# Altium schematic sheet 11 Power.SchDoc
size 420 x 297 mm; DocumentNumber: 11; SheetNumber: 11; SheetTotal: 12
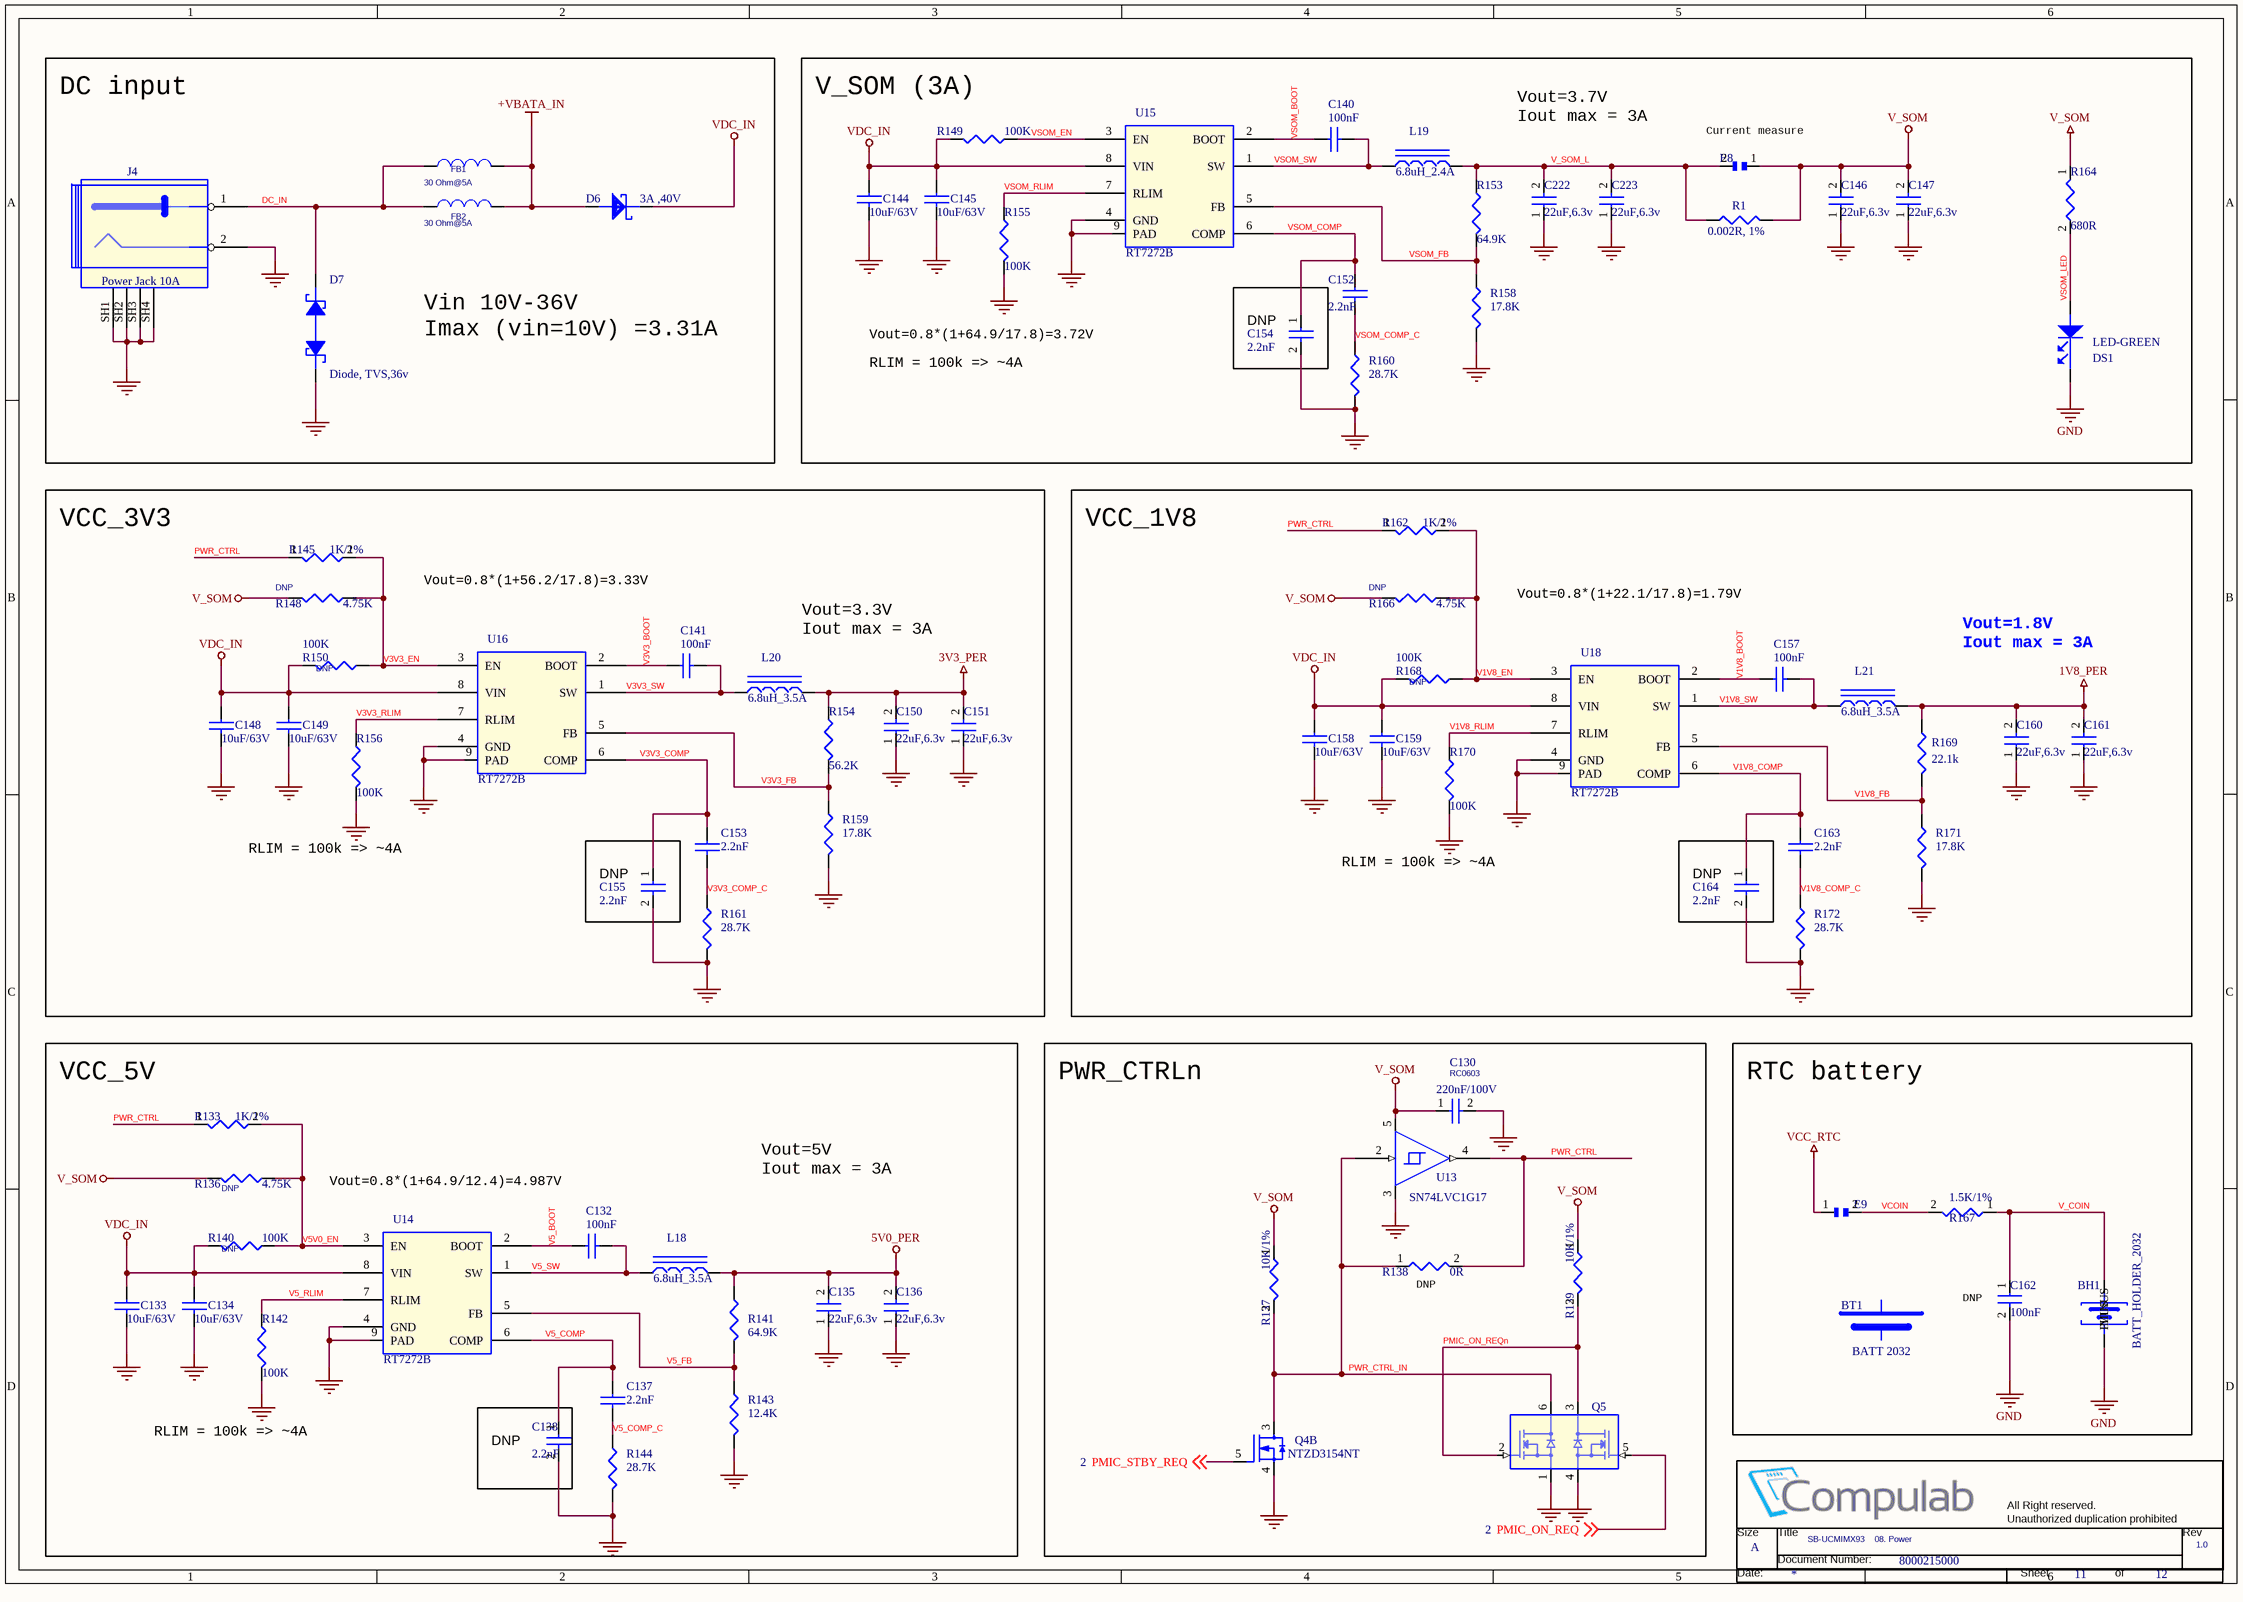
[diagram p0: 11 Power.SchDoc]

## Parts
*  Title: SB-UCMIMX93    08. Power  Doc: 8000215000  RevCode: 1.0  Page Size: A  Page Number: 11  Page Count: 12  (hidden comment: CompuLabTitleBlk)  (graphical)
BH1  BATT_HOLDER_2032  [BATTH20MM]
BT1  BATT 2032  [1X2THHDR]  (mechanical)
C130  220nF/100V  [RC0603]
C132  100nF  [RC0402]
C133  10uF/63V  [C1210H2_5]
C134  10uF/63V  [C1210H2_5]
C135  22uF,6.3v  [RC0603]
C136  22uF,6.3v  [RC0603]
C137  2.2nF  [RC0402]
C138  2.2nF  [RC0402]
C140  100nF  [RC0402]
C141  100nF  [RC0402]
C144  10uF/63V  [C1210H2_5]
C145  10uF/63V  [C1210H2_5]
C146  22uF,6.3v  [RC0603]
C147  22uF,6.3v  [RC0603]
C148  10uF/63V  [C1210H2_5]
C149  10uF/63V  [C1210H2_5]
C150  22uF,6.3v  [RC0603]
C151  22uF,6.3v  [RC0603]
C152  2.2nF  [RC0402]
C153  2.2nF  [RC0402]
C154  2.2nF  [RC0402]
C155  2.2nF  [RC0402]
C157  100nF  [RC0402]
C158  10uF/63V  [C1210H2_5]
C159  10uF/63V  [C1210H2_5]
C160  22uF,6.3v  [RC0603]
C161  22uF,6.3v  [RC0603]
C162  100nF  [RC0402]
C163  2.2nF  [RC0402]
C164  2.2nF  [RC0402]
C222  22uF,6.3v  [RC0603]
C223  22uF,6.3v  [RC0603]
D6  3A ,40V  [DO-214AC]
D7  Diode, TVS,36v  [SOD-323]
DS1  LED-GREEN  [LED-1206]
E8  HDR1X2  [1X2THHDR]  (value not drawn)
E9  HDR1X2  [1X2THHDR]  (value not drawn)
FB1  30 Ohm@5A  [FB0603]
FB2  30 Ohm@5A  [FB0603]
J4  Power Jack 10A  [PJ-0810-TH]
L18  6.8uH_3.5A  [IND6x5_5x3]
L19  6.8uH_2.4A  [IND6x5_5x3]
L20  6.8uH_3.5A  [IND6x5_5x3]
L21  6.8uH_3.5A  [IND6x5_5x3]
Q4  NTZD3154NT  [SOT-563-6]  (part B of 2)
Q5  0.5A,20V,Vgs max 6V  [SOT-563-6]  (value not drawn)
R1  0.002R, 1%  [R1206]
R133  1K/1%  [RC0402]
R136  4.75K  CLABCONF0: DNP  [RC0402]
R137  10K/1%  [RC0402]
R138  0R  [RC0402]
R139  10K/1%  [RC0402]
R140  100K  CLABCONF0: DNP  [RC0402]
R141  64.9K  [RC0402]
R142  100K  [RC0402]
R143  12.4K  [RC0402]
R144  28.7K  [RC0402]
R145  1K/1%  [RC0402]
R148  4.75K  CLABCONF0: DNP  [RC0402]
R149  100K  [RC0402]
R150  100K  CLABCONF0: DNP  [RC0402]
R153  64.9K  [RC0402]
R154  56.2K  [RC0402]
R155  100K  [RC0402]
R156  100K  [RC0402]
R158  17.8K  [RC0402]
R159  17.8K  [RC0402]
R160  28.7K  [RC0402]
R161  28.7K  [RC0402]
R162  1K/1%  [RC0402]
R164  680R  [RC0402]
R166  4.75K  CLABCONF0: DNP  [RC0402]
R167  1.5K/1%  [RC0402]
R168  100K  CLABCONF0: DNP  [RC0402]
R169  22.1k  [RC0402]
R170  100K  [RC0402]
R171  17.8K  [RC0402]
R172  28.7K  [RC0402]
U13  SN74LVC1G17  [SC70]
U14  RT7272B  [PSOP-8-2X2]
U15  RT7272B  [PSOP-8-2X2]
U16  RT7272B  [PSOP-8-2X2]
U18  RT7272B  [PSOP-8-2X2]

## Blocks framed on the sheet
DC input: D6 D7 FB1 FB2 J4
V_SOM (3A): C140 C144-C147 C152 C222 C223 DS1 E8 L19 R1 R149 R153 R155 R158 R160 R164 U15
DNP: C154
VCC_3V3: C141 C148-C151 C153 L20 R145 R148 R150 R154 R156 R159 R161 U16
VCC_1V8: C157-C161 C163 L21 R162 R166 R168-R172 U18
DNP: C155
DNP: C164
VCC_5V: C132-C137 L18 R133 R136 R140-R144 U14
PWR_CTRLn: C130 Q4 Q5 R137-R139 U13
RTC battery: BH1 BT1 C162 E9 R167
DNP: C138

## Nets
1V8_PER: C160.2 C161.2 L21.2 R169.1
3V3_PER: C150.2 C151.2 L20.2 R154.1
5V0_PER: C135.2 C136.2 L18.2 R141.1
+VBATA_IN: D6.ANODE FB1.2 FB2.2
GND: BH1.1(MINUS) C130.2 C133.2 C134.2 C135.1 C136.1 C138.2 C144.2 C145.2 C146.1 C147.1 C148.2 C149.2 C150.1 C151.1 C154.2 C155.2 C158.2 C159.2 C160.1 C161.1 C162.2 C164.2 C222.1 C223.1 D7.ANODE DS1.CATHODE J4.2(R) J4.SH1 J4.SH2 J4.SH3 J4.SH4 Q4.4(S) Q5.1(S1) Q5.4(S2) R142.2 R143.2 R144.2 R155.2 R156.2 R158.2 R159.2 R160.2 R161.2 R170.2 R171.2 R172.2 U13.3(GND) U14.4(GND) U14.9(PAD) U15.4(GND) U15.9(PAD) U16.4(GND) U16.9(PAD) U18.4(GND) U18.9(PAD)
V_SOM: C130.1 C146.2 C147.2 E8.1 R1.2 R136.2 R137.1 R139.1 R148.2 R164.1 R166.2 U13.5(VCC)
VCC_RTC: E9.1
VDC_IN: C133.1 C134.1 C144.1 C145.1 C148.1 C149.1 C158.1 C159.1 D6.CATHODE R140.2 R149.2 R150.2 R168.2 U14.8(VIN) U15.8(VIN) U16.8(VIN) U18.8(VIN)
DC_IN: D7.CATHODE FB1.1 FB2.1 J4.1(CENTRAL)
PMIC_ON_REQ: Q5.5(G2) ; off-sheet PMIC_ON_REQ
PMIC_ON_REQn: Q5.2(G1) Q5.3(D2) R139.2
PMIC_STBY_REQ: Q4.5(G) ; off-sheet PMIC_STBY_REQ
PWR_CTRL: R133.1 R138.2 R145.1 R162.1 U13.4(Y)
PWR_CTRL_IN: Q4.3(D) Q5.6(D1) R137.2 R138.1 U13.2(A)
V1V8_BOOT: C157.1 U18.2(BOOT)
V1V8_COMP: C163.1 C164.1 U18.6(COMP)
V1V8_COMP_C: C163.2 R172.1
V1V8_EN: R162.2 R166.1 R168.1 U18.3(EN)
V1V8_FB: R169.2 R171.1 U18.5(FB)
V1V8_RLIM: R170.1 U18.7(RLIM)
V1V8_SW: C157.2 L21.1 U18.1(SW)
V3V3_BOOT: C141.1 U16.2(BOOT)
V3V3_COMP: C153.1 C155.1 U16.6(COMP)
V3V3_COMP_C: C153.2 R161.1
V3V3_EN: R145.2 R148.1 R150.1 U16.3(EN)
V3V3_FB: R154.2 R159.1 U16.5(FB)
V3V3_RLIM: R156.1 U16.7(RLIM)
V3V3_SW: C141.2 L20.1 U16.1(SW)
V5_BOOT: C132.1 U14.2(BOOT)
V5_COMP: C137.1 C138.1 U14.6(COMP)
V5_COMP_C: C137.2 R144.1
V5_FB: R141.2 R143.1 U14.5(FB)
V5_RLIM: R142.1 U14.7(RLIM)
V5_SW: C132.2 L18.1 U14.1(SW)
V5V0_EN: R133.2 R136.1 R140.1 U14.3(EN)
V_COIN: BH1.2(PLUS) C162.1 R167.1
V_SOM_L: C222.2 C223.2 E8.2 L19.2 R1.1 R153.1
VCOIN: E9.2 R167.2
VSOM_BOOT: C140.1 U15.2(BOOT)
VSOM_COMP: C152.1 C154.1 U15.6(COMP)
VSOM_COMP_C: C152.2 R160.1
VSOM_EN: R149.1 U15.3(EN)
VSOM_FB: R153.2 R158.1 U15.5(FB)
VSOM_LED: DS1.ANODE R164.2
VSOM_RLIM: R155.1 U15.7(RLIM)
VSOM_SW: C140.2 L19.1 U15.1(SW)

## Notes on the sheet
- Vout=3.7V
  Iout max = 3A
- (near E8) Current measure
- Vin 10V-36V
  Imax (vin=10V) =3.31A
- Vout=0.8*(1+64.9/17.8)=3.72V
- RLIM = 100k => ~4A
- Vout=0.8*(1+56.2/17.8)=3.33V
- Vout=3.3V
  Iout max = 3A
- Vout=0.8*(1+22.1/17.8)=1.79V
- Vout=1.8V
  Iout max = 3A
- Vout=0.8*(1+64.9/12.4)=4.987V
- Vout=5V
  Iout max = 3A
- (near R138) DNP
- (near C162) DNP

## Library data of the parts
BH1 = BATT_HOLDER_0: P/N: 190Z00201
BT1 = BATT 2032: P/N: 210C30002
C130 = 100nF, 10V, X7R, 10%, 0402_Dup1: P/N: 151E22410S
C132 C140 C141 C157 = 100nF, 10V, X7R, 10%, 0402_0: P/N: 151B10400S; Group: LAN2
C133 C134 C148 C149 C158 C159 = 22uF/25V: P/N: 151E10680S
C135 C136 C146 C147 C150 C151 C160 C161 C222 C223 = 100nF, 10V, X7R, 10%, 0402: P/N: 151B22610S
C137 C152 C153 C163 = 2.2nF, 50V, X7R, 10%, 0402: P/N: 151D22200S
C138 C154 C155 C164 = 2.2nF, 50V, X7R, 10%, 0402_Dup1: P/N: 151D22200S; CLABCONF0: DNP
C144 C145 = 22uF/25V: P/N: 151D10630S
C162 = 100nF, 10V, X7R, 10%, 0402_Dup1: P/N: 151B10400S; CLABCONF0: DNP
D6 = Diode Shotky,5A,30V_0: P/N: 130E40001S
D7 = 1A Schottky Barrier Rectifier_1: P/N: 132D10080S
DS1 = LED-GREEN 1206_2: P/N: 139A10020S
E8 E9 = HDR 1x2 100MIL TH JUMPER: P/N: 190C00200
FB1 FB2 = Ferrite bead , 30 Ohm@5A: P/N: 147D30000S
J4 = DC Jack ,5.5/2.5,10A,20V: P/N: 180K00200
L18 L20 L21 = IND 6.8uH 3.5A: P/N: 147A6R802S
L19 = IND 6.8uH 3.5A: P/N: 147A6R804S
Q4 = N-MOSFET_Dual: P/N: 131D31540S
Q5 = DUAL N-MOSFET, 0.5A 20V: P/N: 131D31540S
R1 = RESISTOR: P/N: 161F00211S
R133 R145 R162 = 1K,1%,0402,1/16W: P/N: 161C10011S; Group: CAN
R136 R148 R166 = 100K, 0402_0: P/N: 161C47511S
R137 R139 = 10K,1%,0402,1/16W: P/N: 161C10021S
R138 = 0R, 0402: P/N: 161C00005S; CLABCONF0: DNP
R140 R142 R149 R150 R155 R156 R168 R170 = 100K, 0402_0: P/N: 161C10035S
R141 R153 = 10.5K/1%,0402: P/N: 161C64921S
R143 = 2.37K/1%, 0402: P/N: 161C12421S
R144 R160 R161 R172 = 40.2k/1%: P/N: 161C28721S
R154 = 10.5K/1%,0402: P/N: 161C56221S
R158 R159 R171 = 2.37K/1%, 0402: P/N: 161C17821S
R164 = 47K, 0402: P/N: 161C68001S
R167 = 1.5K/1%, 0402: P/N: 161C15011S
R169 = RESISTOR: P/N: 161C22121S
U13 = SN74LVC1G17: P/N: 106D90000S
U14-U16 U18 = RT7272B,Converter,3A,36V: P/N: 123V30000S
